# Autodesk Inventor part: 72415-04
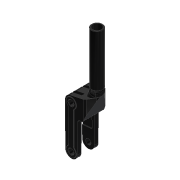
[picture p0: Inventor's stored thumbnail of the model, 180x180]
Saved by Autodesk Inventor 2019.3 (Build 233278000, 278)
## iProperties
Created: 2013-06
Part Number: 72415-04
Material: Ogólny
Document SubType Name: Modeling
Designer: CADENGINEERING4
Density: 1 g/cm^3
Appearance: Gładki — czarny
Author: CADENGINEERING4
Revision Number: ÈÎºÎ
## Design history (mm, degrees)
feature "À­Éì2"
feature "µ¹½Ç2"
node "Bryła1"
node "Bryła2"
